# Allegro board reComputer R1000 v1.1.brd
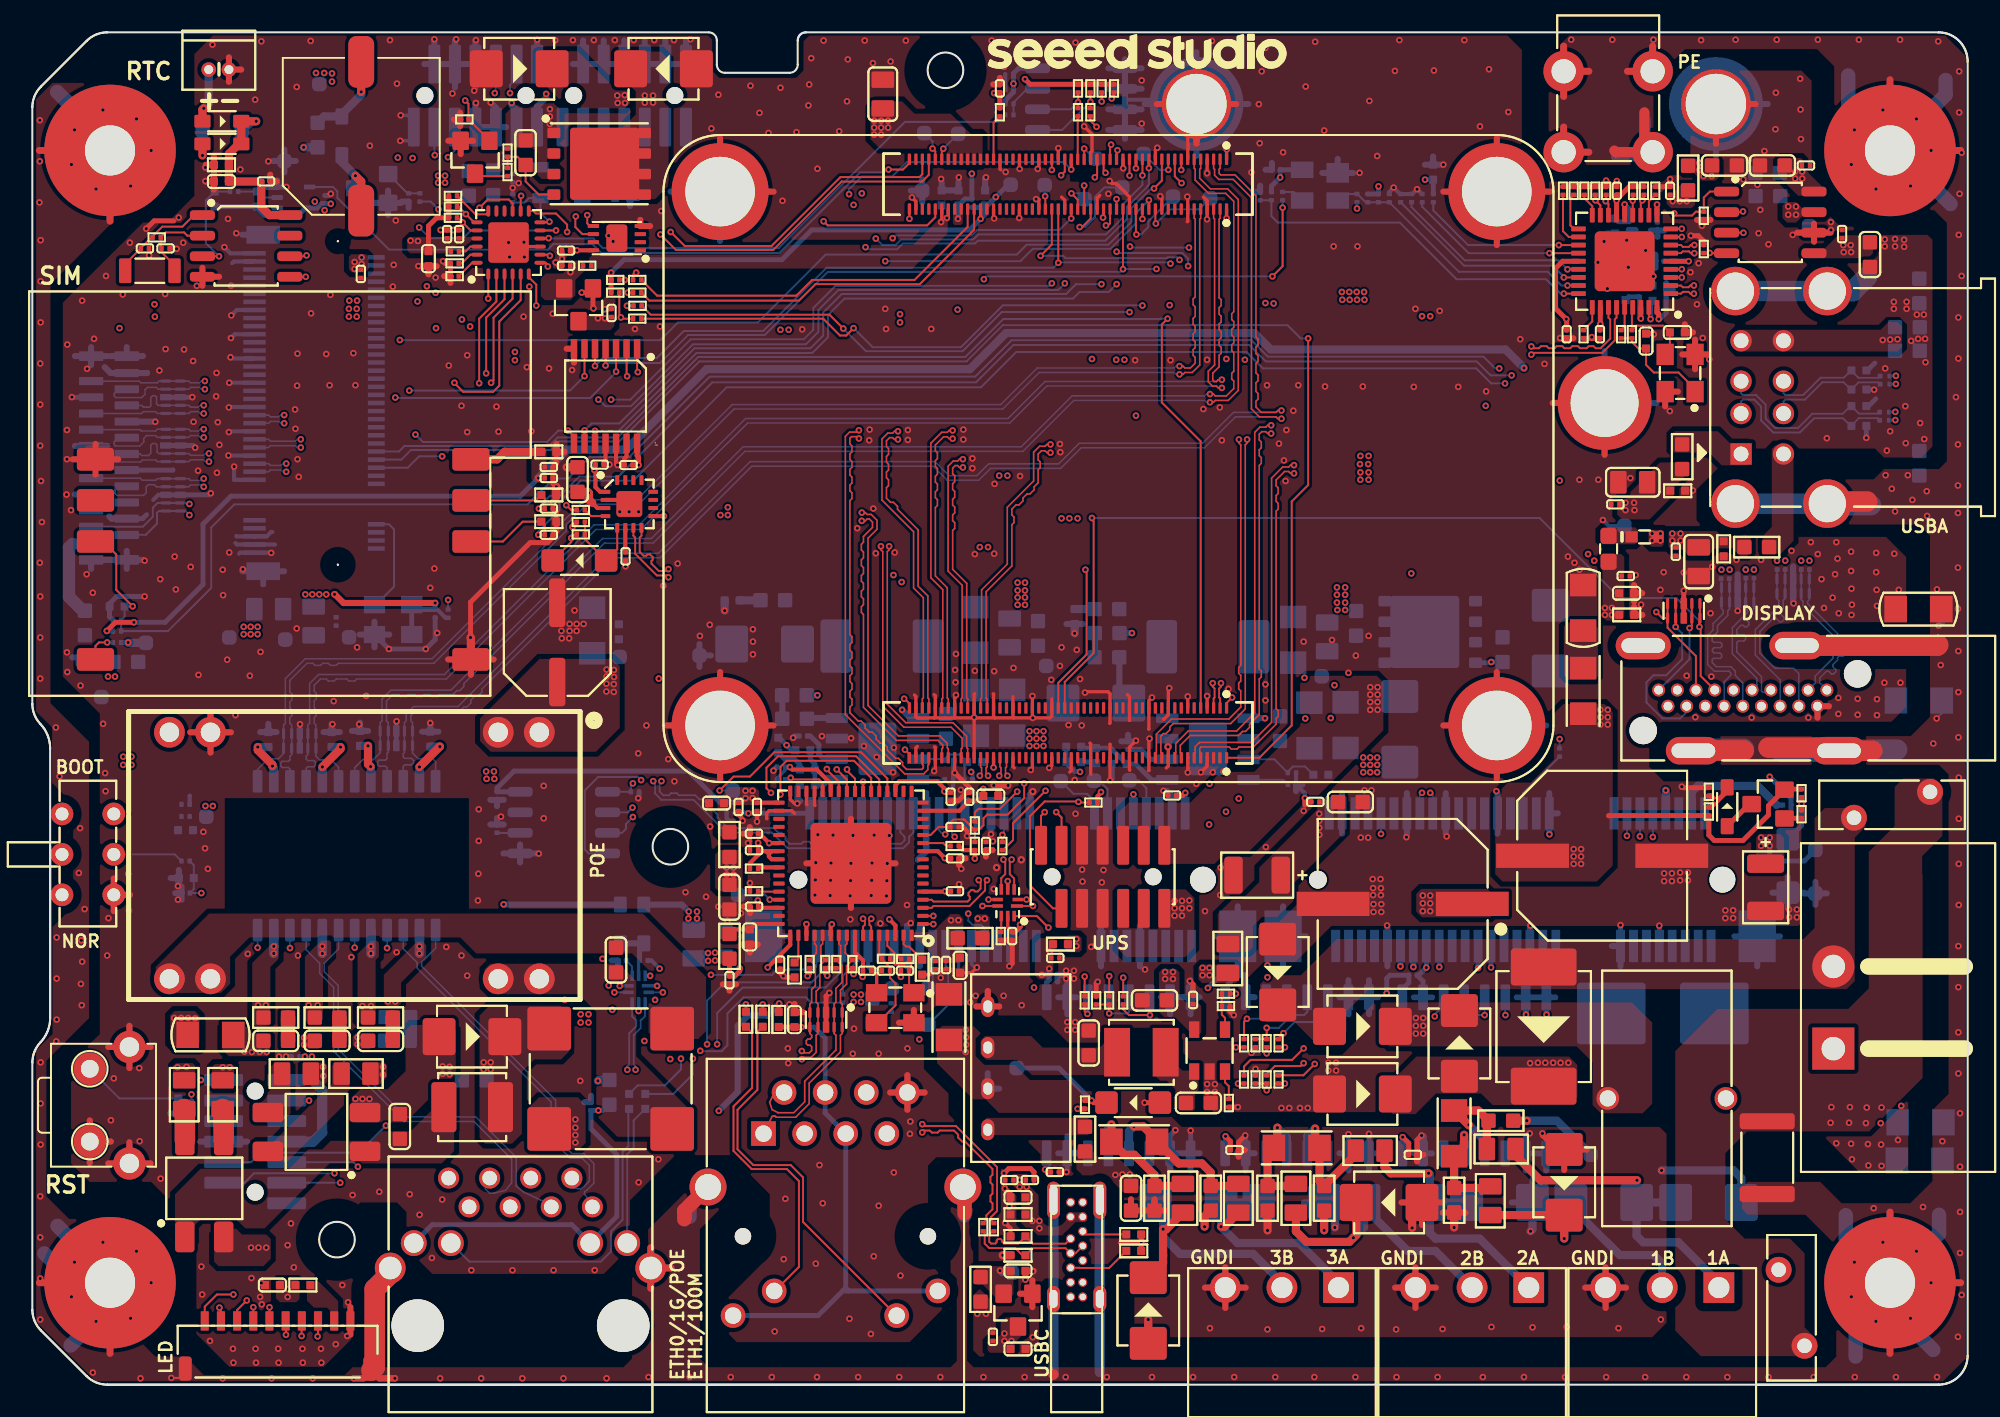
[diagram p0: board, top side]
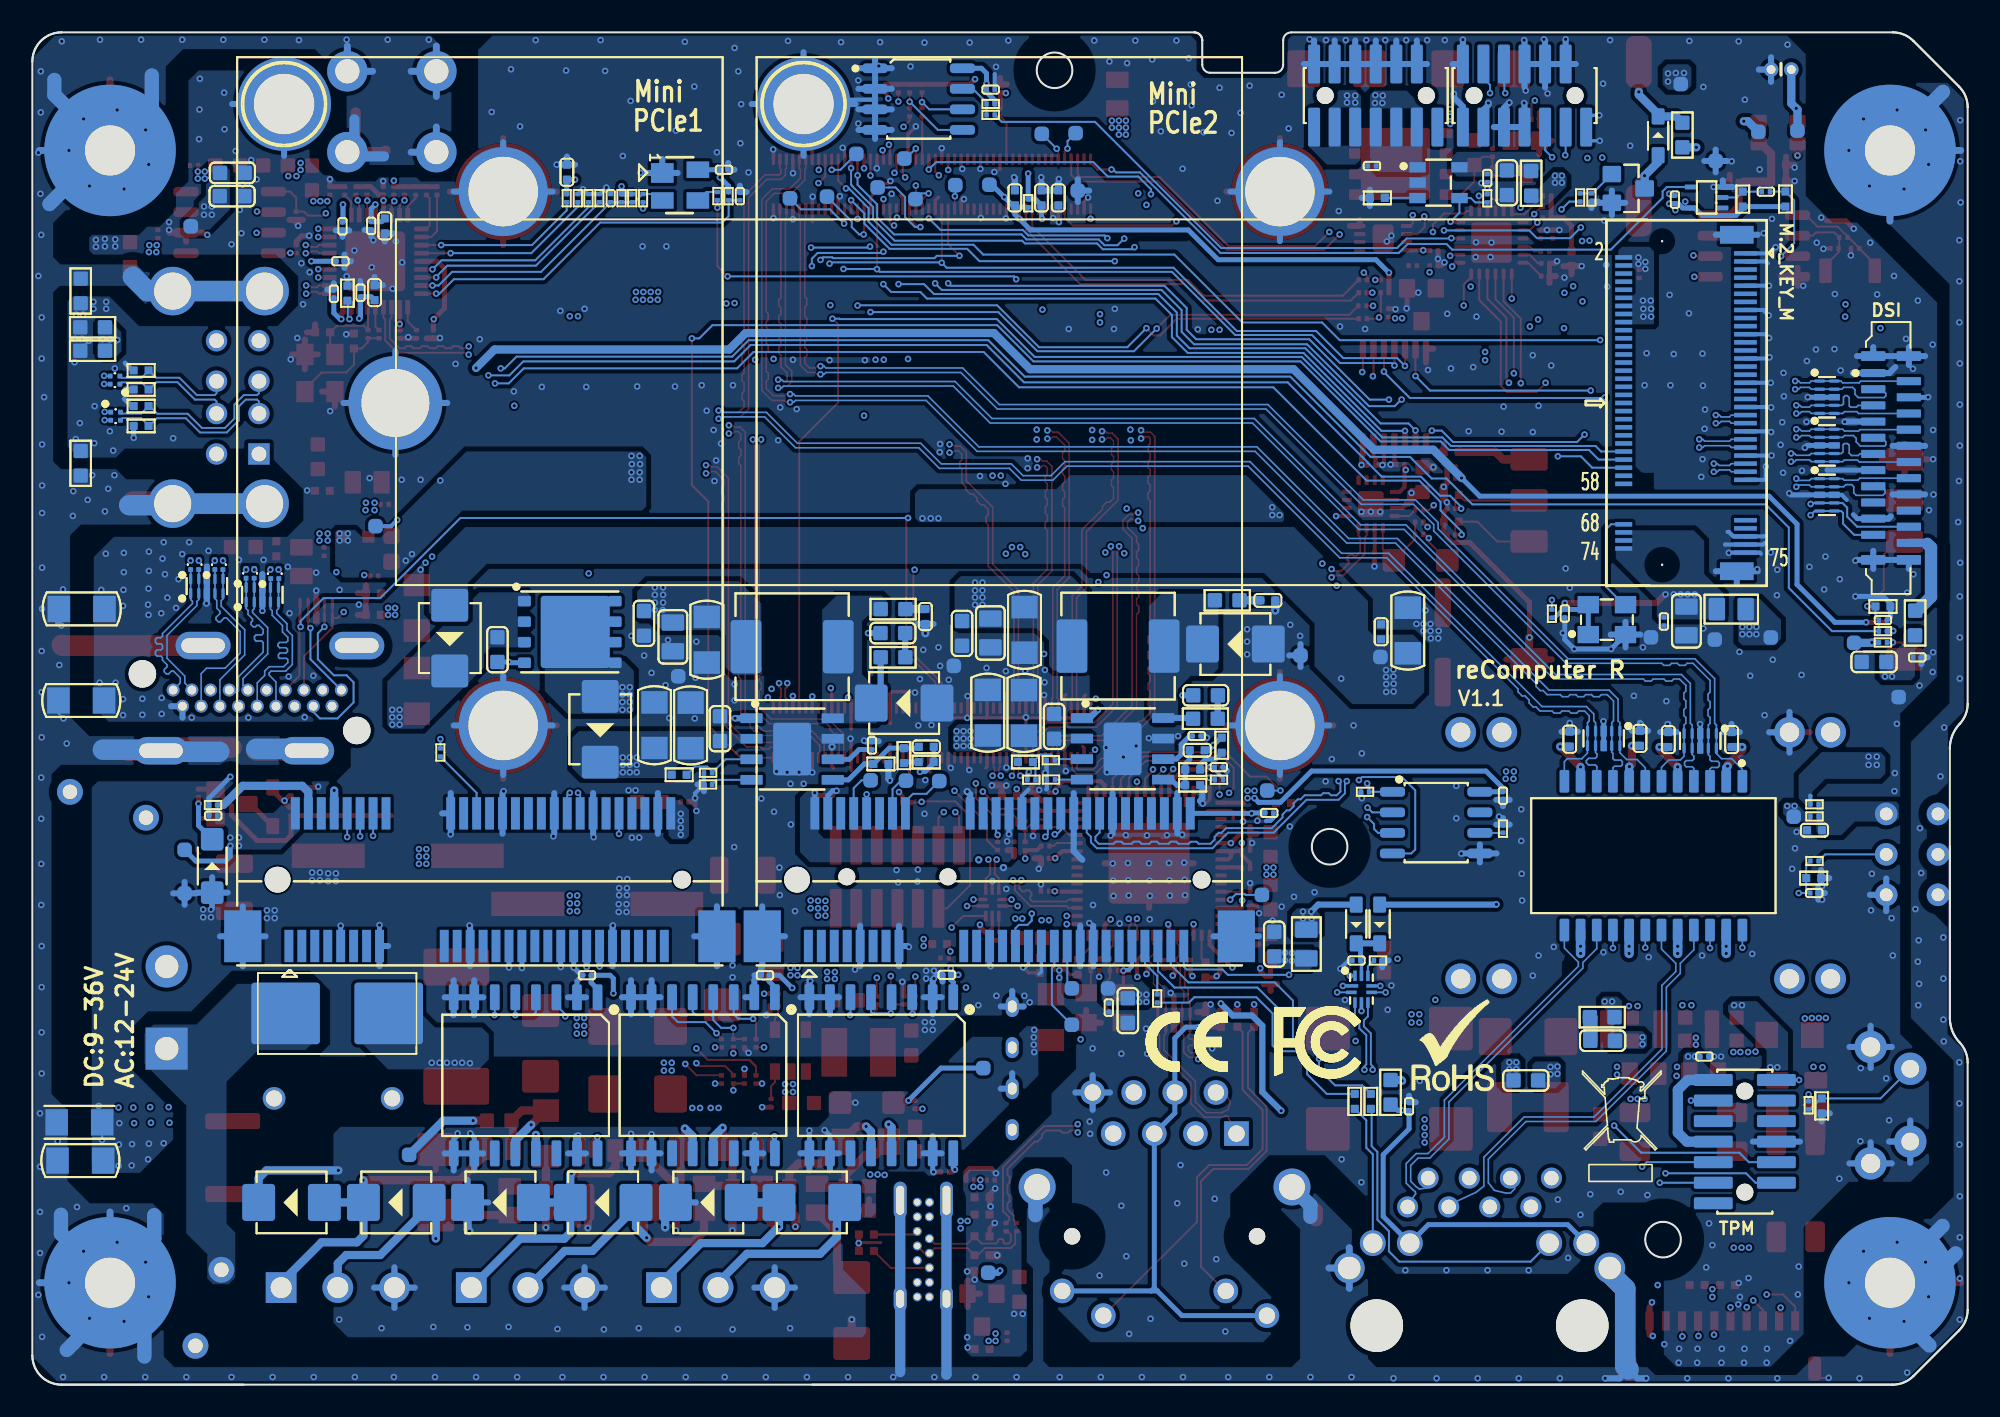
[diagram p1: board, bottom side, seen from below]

Outline 119.6 x 83.6 mm; copper layers: TOP, LYR2_GND, LYR3, LYR4_GND, LYR5_PWR, LYR6, LYR7_GND, BOTTOM. Coordinates in mm from the lower left corner of the outline.
Outline path: circle c18.82,8.97 r1.1 ; circle c18.82,8.97 r1.1 ; circle c39.43,33.26 r1.1 ; circle c39.43,33.26 r1.1 ; circle c56.43,81.25 r1.1 ; circle c56.43,81.25 r1.1 ; 0,78.97 0,42.09 ; 0,78.97 arc(0.14,79.66) 0.53,80.24 ; 0,78.97 arc(0.14,79.66) 0.53,80.24 ; 0,42.09 arc(0.13,41.42) 0.5,40.85 ; 0,42.09 arc(0.13,41.42) 0.5,40.85 ; 0.53,80.24 3.36,83.07 ; 0.53,80.24 3.36,83.07 ; 0,19.91 0,4.63 ; 0,19.91 arc(0.13,20.58) 0.5,21.15 ; 0,19.91 arc(0.13,20.58) 0.5,21.15 ; 0,4.63 arc(0.14,3.94) 0.53,3.36 ; 0,4.63 arc(0.14,3.94) 0.53,3.36 ; 0.5,21.15 arc(0.94,21.85) 1.1,22.67 ; 0.5,21.15 arc(0.94,21.85) 1.1,22.67 ; 0.5,40.85 arc(0.94,40.15) 1.1,39.33 ; 0.5,40.85 arc(0.94,40.15) 1.1,39.33 ; 1.1,39.33 1.1,22.67 ; 3.36,83.07 arc(3.94,83.46) 4.63,83.6 ; 3.36,83.07 arc(3.94,83.46) 4.63,83.6 ; 0.53,3.36 3.36,0.53 ; 0.53,3.36 3.36,0.53 ; 3.36,0.53 arc(3.94,0.14) 4.63,0 ; 3.36,0.53 arc(3.94,0.14) 4.63,0 ; 1.1,22.67 1.1,33.26 ; 4.63,83.6 41.8,83.6 arc(42.15,83.45) 42.3,83.1 42.3,81.6 arc(42.45,81.25) 42.8,81.1 46.8,81.1 arc(47.15,81.25) 47.3,81.6 47.3,83.1 ; 4.63,0 71.42,0 ; 4.63,0 117.8,0 ; 117.8,0 106.52,0 ; 117.8,0 arc(119.07,0.53) 119.6,1.8 ; 117.8,0 arc(119.07,0.53) 119.6,1.8 ; 47.3,83.1 arc(47.45,83.45) 47.8,83.6 ; 47.3,83.1 arc(47.45,83.45) 47.8,83.6 ; 47.8,83.6 117.8,83.6 ; 117.8,83.6 arc(119.07,83.07) 119.6,81.8 ; 117.8,83.6 arc(119.07,83.07) 119.6,81.8 ; 119.6,81.8 119.6,1.8

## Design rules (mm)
constraint set DEFAULT: min track width 0.121
net group CM4_UART2_RXD: nets CM4_UART2_RXD UART2_RXD
net group CM4_UART2_TXD: nets CM4_UART2_TXD UART2_TXD
net group CM4_UART3_RXD: nets CM4_UART3_RXD N23430020
net group CM4_UART3_TXD: nets CM4_UART3_TXD N23430129
net group CM4_UART4_RXD: nets CM4_UART4_RXD N23431044
net group CM4_UART4_TXD: nets CM4_UART4_TXD N23431153
net group DP_HDMI0_CLK_N1: nets HDMI0_CLK_N HDMI0_CLK_P
net group DP_HDMI0_TX0: nets HDMI0_TX0_N HDMI0_TX0_P
net group DP_HDMI0_TX1_N1: nets HDMI0_TX1_N HDMI0_TX1_P
net group DP_HDMI0_TX2_N1: nets HDMI0_TX2_N HDMI0_TX2_P
net group DSI1_C_N: nets DSI1_C_N DSI1_C_P
net group DSI1_D0_N: nets DSI1_D0_N DSI1_D0_P
net group DSI1_D1_P: nets DSI1_D1_N DSI1_D1_P
net group DSI1_D2_N: nets DSI1_D2_N DSI1_D2_P
net group DSI1_D3_N: nets DSI1_D3_N DSI1_D3_P
net group ETHERNET0: nets ETHERNET_PAIR0_N ETHERNET_PAIR0_P
net group ETHERNET1: nets ETHERNET_PAIR1_N ETHERNET_PAIR1_P
net group ETHERNET2: nets ETHERNET_PAIR2_N ETHERNET_PAIR2_P
net group ETHERNET3: nets ETHERNET_PAIR3_N ETHERNET_PAIR3_P
net group ETHERNET_RX_P: nets ETHERNET_RX_N ETHERNET_RX_P
net group ETHERNET_TX_P: nets ETHERNET_TX_N ETHERNET_TX_P
net group HDMI0_CLK_N1: nets HDMI0_CLK_N1 HDMI0_CLK_P1
net group HDMI0_TX0_N1: nets HDMI0_TX0_N1 HDMI0_TX0_P1
net group HDMI0_TX1_N1: nets HDMI0_TX1_N1 HDMI0_TX1_P1
net group HDMI0_TX2_N1: nets HDMI0_TX2_N1 HDMI0_TX2_P1
net group N21891930: nets N21891930 N21894342
net group N23452005: nets N23452005 N23452027
net group PCIE_CLK: nets PCIE_CLK_N PCIE_CLK_P
net group PCIE_RX: nets PCIE_RX_N PCIE_RX_P
net group PCIE_TX: nets PCIE_TX_N PCIE_TX_P
net group RJ_12: nets N22026897 N22026906
net group RJ_36: nets N22026915 N22078660
net group RJ_45: nets N22078676 N22078685
net group RJ_78: nets N22026957 N22026966
net group RS485_2: nets EXT_RS485_2_A EXT_RS485_2_B
net group USB_0: nets USB_0M USB_0P
net group USB_1P: nets USB_1M USB_1P
net group USB_D: nets USB_DM USB_DP
net group USB_HUB1_DM2: nets USB_HUB1_DM2 USB_HUB1_DP2
net group USB_HUB1_DM3: nets USB_HUB1_DM3 USB_HUB1_DP3
net group USB_HUB2_D1: nets USB_HUB2_DM1 USB_HUB2_DP1
net group USB_HUB2_D2: nets USB_HUB2_DM2 USB_HUB2_DP2
net group USB_HUB2_D3: nets USB_HUB2_DM3 USB_HUB2_DP3
net group USB_HUB2_D4: nets USB_HUB2_DM4 USB_HUB2_DP4
net group USB_HUB2_DP1_01: nets N23711005 N23711301
net group USB_HUB2_DP2_01: nets N23452966 N23452985
net group USB_TO_UART: nets USB_TO_UART_DM USB_TO_UART_DP
net group USBC: nets USB_C_DM USB_C_DP
net group USBC_DM: nets USBC_DM USBC_DP
net group VDD33_HUB1: nets N23370571 N23401903
net group 5V_ISO_OUT: nets RS485_1_A RS485_2_A RS485_3_A
net group +3.3V_OUT: nets +3.3V_OUT CM4_GPIO_VREF SD_VDD_OVERRIDE
net group RS485_1: nets RS485_3_B

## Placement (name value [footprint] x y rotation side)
B1  HPD-9603S-3  [BUZZER2P_8D4_9_6X9_6X5_5MM]  20.32 77.18 0 top
C1  100nF  [C0603]  90.86 45.44 270 bottom
C2  220uF  [CAE-10_5X10_5X10_5MM-S]  97.01 32.7 0 top
C3  4.7uF  [C1206]  95.84 48.03 90 top
C5  100nF  [C0603]  66.42 46.46 180 bottom
C6  4.7uF  [C0402]  59.23 36.39 0 top
C7  10uF  [C1206]  78.92 40.76 90 bottom
C8  10uF  [C1206]  81.16 40.77 90 bottom
C9  100nF  [C0603]  77.11 40.55 90 bottom
C10  100nF  [C0603]  81.81 47.07 270 bottom
C11  22uF  [C0805]  80.02 46.23 270 bottom
C12  100uF  [C1206]  77.92 46.05 270 bottom
C13  100uF  [C1206]  58.29 46.66 270 bottom
C14  100nF  [C0201]  44.59 34.06 180 top
C15  10nF  [C0201]  67.71 39.52 90 bottom
C16  150pF  [C0402]  64.41 47.49 270 bottom
C17  150pF  [C0402]  64.35 39.43 0 bottom
C18  100nF  [C0603]  47.09 42.62 180 bottom
C19  100nF  [C0201]  57.9 36.35 90 top
C20  10uF  [C1206]  60.56 41.54 90 bottom
C21  10uF  [C1206]  58.32 41.53 90 bottom
C22  100nF  [C0603]  56.46 40.69 90 bottom
C23  100nF  [C0603]  62.15 46.44 270 bottom
C24  22uF  [C0805]  60.39 46.47 270 bottom
C28  10nF  [C0201]  47.64 40.1 180 bottom
C29  150pF  [C0402]  43.25 48.48 180 bottom
C30  150pF  [C0402]  47.61 39.22 0 bottom
C31  22uF  [C0805]  52.56 79.78 90 top
C32  100nF  [C0201]  59.79 80.13 90 top
C33  10uF  [C0402]  57.23 73.37 270 bottom
C34  10uF  [C0402]  56.2 73.37 270 bottom
C35  1uF  [C0402]  58.88 73.37 270 bottom
C36  1uF  [C0402]  9.47 34.28 0 bottom
C37  100nF  [C0201]  9.48 30.39 180 bottom
C38  100nF  [C0201]  60.56 27.73 270 top
C40  100nF  [C0201]  46.28 38.18 180 bottom
C41  100nF  [C0201]  44.78 35.71 270 top
C42  10uF  [C0603]  43.08 30.14 270 top
C43  100nF  [C0201]  43.64 35.71 270 top
C44  4.7uF  [C0402]  42.28 35.95 180 top
C45  100nF  [C0201]  44.6 29.56 180 top
C46  100nF  [C0201]  44.6 33.04 180 top
C47  100nF  [C0201]  56.75 36.35 270 top
C48  4.7uF  [C0402]  57.33 25.92 270 top
C49  100nF  [C0201]  55.8 25.94 270 top
C50  100nF  [C0201]  51.59 25.59 0 top
C51  100nF  [C0201]  57.02 32.54 0 top
C52  100nF  [C0201]  56.47 25.94 270 top
C53  100nF  [C0201]  46.21 25.97 270 top
C54  100nF  [C0201]  57.02 30.5 0 top
C55  100nF  [C0201]  56.99 34.48 0 top
C56  12pF  [C0201]  53.93 25.59 180 top
C57  12pF  [C0201]  52.75 25.59 180 top
C58  10uF  [C0603]  104.57 75.37 0 top
C59  100nF  [C0201]  101.21 73.81 90 top
C60  100nF  [C0201]  75.88 73.47 90 bottom
C61  100nF  [C0201]  83.86 73.35 90 bottom
C62  100nF  [C0201]  100.43 71.61 270 bottom
C63  100nF  [C0201]  96.88 64.94 270 top
C64  100nF  [C0201]  94.82 64.94 270 top
C65  100nF  [C0201]  100.56 69.45 180 bottom
C66  100nF  [C0201]  100.97 67.44 90 bottom
C67  100nF  [C0201]  97.92 73.81 90 top
C68  100nF  [C0201]  76.86 75.11 180 bottom
C69  1uF  [C0402]  98.45 67.51 270 bottom
C70  10nF  [C0201]  99.32 67.5 270 bottom
C71  1uF  [C0402]  97.82 71.64 90 bottom
C72  10nF  [C0201]  98.66 71.64 90 bottom
C73  1uF  [C0402]  86.57 74.96 90 bottom
C74  27pF  [C0402]  99.73 64.52 90 top
C75  27pF  [C0402]  101.66 65.05 0 top
C76  10uF  [C0805]  98.9 55.79 0 top
C77  10uF  [C0805]  102.98 50.88 270 top
C78  100nF  [C0201]  97.83 54.42 0 top
C79  100nF  [C0201]  101.56 51.5 270 top
C80  10uF  [C0603]  107.26 73.47 180 bottom
C81  10uF  [C0603]  107.24 74.91 180 bottom
C82  10uF  [C0603]  107.53 75.37 180 top
C83  100nF  [C0201]  109.61 75.37 0 top
C84  10uF  [C0603]  113.56 69.86 270 top
C85  100nF  [C0201]  111.84 71.13 90 top
C86  100nF  [C0201]  98.47 49.99 0 top
C87  1uF  [C0402]  98.52 48.92 0 top
C88  22nF  [C0402]  47.1 22.57 90 top
C89  1uF  [C0402]  24.48 69.61 270 top
C90  100nF  [C0201]  26.38 71.13 90 top
C91  100nF  [C0201]  25.63 71.13 90 top
C92  1uF  [C0402]  60.91 11.58 180 top
C93  100nF  [C0201]  61.65 12.65 0 top
C94  100nF  [C0201]  60.38 12.65 180 top
C95  1uF  [C0402]  60.91 2.21 0 top
C96  100nF  [C0201]  59.36 2.96 90 top
C97  1uF  [C0402]  60.91 7.03 0 top
C98  100nF  [C0201]  37.77 26.22 0 bottom
C99  10uF  [C0603]  33.69 55.95 270 top
C100  100nF  [C0201]  35.06 56.87 180 top
C101  100nF  [C0201]  36.66 51.2 90 top
C102  18pF  [C0201]  8.23 70.24 180 top
C103  18pF  [C0201]  6.95 70.24 0 top
C104  1uF  [C0402]  11.68 74.38 180 top
C105  100nF  [C0201]  14.44 74.39 0 top
C106  100nF  [C0201]  16.27 20.28 180 bottom
C107  100nF  [C0201]  60.38 80.06 180 bottom
C108  100nF  [C0201]  18.09 73.26 90 bottom
C109  100nF  [C0201]  12.47 73.75 0 bottom
C110  100nF  [C0201]  32.98 70.11 0 top
C111  100nF  [C0201]  108.43 35.17 0 bottom
C112  100nF  [C0201]  70.44 36.42 0 top
C113  100nF  [C0201]  53.08 23.31 90 bottom
C114  100nF  [C0201]  43.16 35.34 0 bottom
C115  100nF  [C0201]  35.79 66.26 270 top
C116  100nF  [C0201]  32.99 69.17 0 top
C117  10uF  [C0603]  42.85 27.23 90 bottom
C118  10uF  [C0603]  51.9 23.13 270 bottom
C119  100nF  [C0201]  58.93 33.3 270 top
C120  100nF  [C0201]  31.92 56.73 0 top
C121  33pF  [C0201]  31.92 56.05 0 top
C122  33pF  [C0201]  5.23 47.27 180 bottom
C123  33pF  [C0201]  31.92 52.54 0 top
C124  10uF  [C0603]  81.45 36.02 0 top
C125  100nF  [C0201]  79.29 36.03 180 top
C126  47uF  [AVX_B]  75.69 31.5 180 top
C127  47uF  [AVX_B]  107.11 30.75 270 top
C128  33pF  [C0201]  31.92 54.16 0 top
C130  10uF  [C0603]  69.35 23.76 180 top
C131  100nF  [C0201]  71.73 23.78 90 top
C132  10uF  [C0603]  72.06 17.42 0 top
C133  10uF  [C0603]  65.28 21.12 90 top
C134  10uF  [C0603]  67.9 11.52 270 top
C136  100nF  [C0201]  63.22 26.38 0 top
C137  100nF  [C0201]  85.32 25.31 0 bottom
C138  100nF  [C0201]  85.32 14.21 0 top
C139  100nF  [C0201]  36.84 56.85 180 top
C140  100nF  [C0201]  74.32 25.31 0 bottom
C141  100nF  [C0201]  74.29 14.51 0 top
C142  100nF  [C0201]  63.1 25.34 0 bottom
C143  100nF  [C0201]  63.19 13.15 0 top
C144  100uF  [ELECTRO_SMD_6_6X6_6MM]  32.44 45.88 0 top
C145  10uF  [C1206]  34.6 46.62 90 bottom
C146  100nF  [C0402]  36.25 46.54 90 bottom
C147  10nF  [C0603]  36.07 26.25 90 top
C148  10nF  [C0603]  27.31 18.81 180 bottom
C149  10nF  [C0603]  22.71 15.96 90 top
C150  100nF  [C0402]  14.58 39.88 90 bottom
C151  100nF  [C0402]  18.5 39.88 90 bottom
C152  100nF  [C0402]  20.25 39.96 90 bottom
C153  100nF  [C0402]  24.59 39.91 90 bottom
C154  22nF  [C0603]  15.04 21.26 180 top
C155  22nF  [C0603]  18.21 21.26 180 top
C156  22nF  [C0603]  21.52 21.26 180 top
C157  22nF  [C0603]  22.56 21.26 180 bottom
C158  1nF  [C1206]  11.01 21.62 180 top
C159  1nF  [C1206]  116.63 13.85 0 bottom
C160  100nF  [C0201]  34.52 17.21 90 bottom
C161  100nF  [C0201]  36.81 75.34 0 bottom
C162  100nF  [C0603]  30.48 76.16 270 top
C163  4.7uF  [C0402]  14.84 6.16 180 top
C164  10uF  [C0603]  28.48 74.3 270 bottom
C165  100nF  [C0201]  29.69 74.59 270 bottom
C166  22uF  [C0805]  17.38 47.21 270 bottom
C167  100nF  [C0201]  18.77 47.18 270 bottom
C168  100nF  [C0201]  24.89 47.67 270 bottom
C169  100nF  [C0201]  20.3 68.67 270 top
C499  220uF  [CAE-10_5X10_5X10_5MM-S]  84.69 29.72 180 top
C500  100nF  [C0201]  28.72 36.41 270 bottom
C501  100nF  [C0201]  43.08 25 270 top
C502  1uF  [C0402]  44.33 27.68 270 top
C503  10uF  [C0603]  5.78 44.68 0 bottom
C504  100nF  [C0201]  3.11 44.96 180 bottom
C505  1nF  [C1206]  116.58 42.29 0 bottom
C506  10nF  [C1206]  116.55 47.96 0 bottom
C507  10nF  [C1206]  116.56 47.94 0 top
D1  SM360B  [DO_214AA_SMB]  93.8 46.15 270 bottom
D2  SM360B  [DO_214AA_SMB]  84.51 40.51 270 bottom
D3  SM360B  [DO_214AA_SMB]  88.19 21.09 90 top
D4  SM360B  [DO_214AA_SMB]  82.2 22.15 0 top
D5  SMCJ40A  [DO_214AB_SMC]  93.4 22.14 270 top
D6  SM360B  [DO_214AA_SMB]  82.2 17.97 0 top
D7  SM360B  [DO_214AA_SMB]  76.96 25.51 270 top
D8  MMSZ5259A  [SOD_123]  108.49 32.07 90 bottom
D9  B5819WS SL  [SOD_323]  104.74 35.72 90 top
D10  SM360B  [DO_214AA_SMB]  65.73 42.14 0 bottom
D11  SM360B  [DO_214AA_SMB]  45.25 45.78 0 bottom
D12  ESDPSA0402V05  [D0402]  9.02 17.23 90 bottom
D13  B5819WS SL  [SOD_323]  19.13 77.2 90 bottom
D14  ESDPSA0402V05  [D0402]  112.88 60.5 180 bottom
D15  ESDPSA0402V05  [D0402]  112.88 59.27 180 bottom
D16  ESDPSA0402V05  [D0402]  101.68 55.26 180 top
D17  ESDPSA0402V05  [D0402]  104.52 51.67 90 top
D18  ESDPSA0402V05  [D0402]  112.88 61.52 180 bottom
D19  ESDPSA0402V05  [D0402]  112.88 62.7 180 bottom
D20  ESDPSA0402V05  [D0402]  98.53 47.59 180 top
D21  ESDPSA0402V05  [D0402]  60.91 10.52 0 top
D22  ESDPSA0402V05  [D0402]  60.91 8 0 top
D23  ESDPSA0402V05  [D0402]  60.91 9.17 0 top
D24  B5819WS SL  [SOD_323]  36.34 28.48 270 bottom
D25  B5819WS SL  [SOD_323]  37.79 28.48 270 bottom
D26  B0540W  [SOD_123]  33.81 50.95 180 top
D27  B5819WS SL  [SOD_323]  11.71 76.71 0 top
D28  ESDPSA0402V05  [D0402]  11.69 75.41 0 top
D29  B5819WS SL  [SOD_323]  11.71 78.1 0 top
D30  TPD1E1B04DPYR  [D0402]  5.23 48.11 0 bottom
D31  TPD1E1B04DPYR  [D0402]  31.92 53.35 180 top
D32  TPD1E1B04DPYR  [D0402]  31.92 55 180 top
D33  TPD1E1B04DPYR  [D0402]  31.92 57.67 180 top
D34  MMSZ5232BT1G  [SOD_123]  68.03 17.43 180 top
D36  SMBJ13CATR7  [DO_214AA_SMB]  103.58 11.26 0 bottom
D37  SMBJ13CATR7  [DO_214AA_SMB]  97.11 11.26 0 bottom
D39  SMBJ13CATR7  [DO_214AA_SMB]  94.67 12.51 270 top
D41  SMBJ13CATR7  [DO_214AA_SMB]  90.67 11.26 0 bottom
D42  SMBJ13CATR7  [DO_214AA_SMB]  84.33 11.26 0 bottom
D44  SMBJ13CATR7  [DO_214AA_SMB]  83.85 11.26 180 top
D46  SMBJ13CATR7  [DO_214AA_SMB]  77.83 11.26 0 bottom
D47  SMBJ13CATR7  [DO_214AA_SMB]  71.43 11.26 0 bottom
D48  SMBJ13CATR7  [DO_214AA_SMB]  68.96 4.58 90 top
D50  SMBJ58CA  [DO_214AA_SMB]  27.17 21.51 0 top
D51  MB6S  [SMD4P_4D7X3D8MM]  10.62 12.13 180 top
D52  MB6S  [SMD4P_4D7X3D8MM]  17.56 15.62 270 top
D61  SMBJ36CA  [DO_214AA_SMB]  39.01 81.35 180 top
D62  SMBJ5.0CA-TR  [DO_214AA_SMB]  30.09 81.35 0 top
D63  LRB520S-30T1G  [SOD_523]  99.64 52.41 180 top
F1  5A  [FUSE2P_HOLDER_9_73X5_03X3_81MM]  100.76 22.95 180 bottom
F2  100mA  [F0603]  97.41 51.67 90 top
FB1  120R  [L0603]  43.08 33.39 90 top
FB2  120R  [L0603]  57.95 27.6 180 top
FB3  120R  [L0603]  43.08 27.1 270 top
FB4  120R  [L0603]  102.33 74.6 270 top
FB5  120R  [L0603]  101.96 57.37 90 top
FB6  120R  [L0603]  106.56 51.78 180 top
FB9  120R  [L0603]  35.66 18.07 270 bottom
FB10  120R  [L0603]  26.98 74.27 90 bottom
FB26  120R  [L0603]  3.24 47.09 270 bottom
FB27  120R  [L0402]  16.72 6.16 180 top
G1  4532-201-LF  [GDT2P_4D0_4_5X3_2X2_7MM]  107.22 14.03 90 top
J1  STP2EDGRM-X-5.08-2P  [TERMINAL_2P_5D08]  111.3 23.31 90 top
J2  Header 2x7Pin 1.27MM  [HEADER2X7P_1D27_SMD_NP_EPT14]  66.14 31.4 180 top
J3  PCB-69-M3  [SOLDERING_TERMINAL_4P_9X6_3X5MM]  97.38 78.69 270 top
J4  DF40C-100DS-0.4V(51)  [DF40_100P_0D4_22_6X3_38X1_5MM]  64 74.21 90 top
J5  DF40C-100DS-0.4V(51)  [DF40_100P_0D4_22_6X3_38X1_5MM_101_200]  64 40.29 90 top
J6  Toggle Switch_2CH  [SW6P_2D5_9X3_5X3_5MM]  3.43 32.78 270 top
J8  USB-AF-90  [ST-USB-201C]  110.93 61.03 270 top
J9  TYPE_A  [HDMI19P_1D155_23_1X7_7X16_4MM]  112.8 42.44 90 top
J10  LPJ0011BBNL  [RJ45-7499010211A]  45.19 15.52 0 top
J11  UBF31-112-14C1-024  [USB2_0_TYPE_C_14X3D16X8D94MM]  64.54 8.35 270 top
J12  Header 1x2 1.25mm  [HEADER2P_1D25_DIP]  11.52 81.3 0 top
J13  Header 2x7Pin 1.27MM  [HEADER2X7P_1D27_SMD_NP_EPT14]  13.77 15.02 270 bottom
J14  ST-PC-009  [PCIE52_0D8_56X30_2X4MM]  59.84 31.22 90 bottom
J15  ST-PC-009  [PCIE52_0D8_56X30_2X4MM]  91.95 31.22 90 bottom
J16  ST-SIM-10CY  [SIM6_2P_2D54_25X31X3_55MM]  3.9 57.2 270 top
J18  DGKYD56A1188AB1A2DY1054  [RJ45_12_2P_2D54_16_3X15_8X12_85MM]  30.17 3.65 0 top
J19  Header 2x7Pin 1.27MM  [HEADER2X7P_1D27_SMD_NP_EPT14]  36.58 79.69 180 bottom
J21  HQ15EDGRC-3.5-03P-040  [TERMINAL_3P_3D5_11_6X9_2X7_3MM]  100.72 6 180 top
J22  HQ15EDGRC-3.5-03P-040  [TERMINAL_3P_3D5_11_6X9_2X7_3MM]  88.97 6 180 top
J23  HQ15EDGRC-3.5-03P-040  [TERMINAL_3P_3D5_11_6X9_2X7_3MM]  77.22 6 180 top
J24  MTFP65-822SWN-19A72  [FPC22_0D5_16_7X3_5X3_95MM_90D]  4.73 57.29 90 bottom
J25  1.0-10A-LT  [JST10_2P_1D0_12_35X3_2X4_5MM]  15.15 3.94 0 top
J61  Header 2x7Pin 1.27MM  [HEADER2X7P_1D27_SMD_NP_EPT14]  27.38 79.69 180 bottom
J62  2E0BC26-F20BM-7H  [CON_MINIPEX_075_SMT_RA_M2_KEYM]  17.55 60.69 270 bottom
L2  10uH  [L6_6X7X1_6MM]  72.65 45.62 0 bottom
L3  10uH  [L6_6X7X1_6MM]  52.5 45.66 0 bottom
L4  90R  [L4P_0_85X0_65MM]  114.46 59.87 270 bottom
L5  90R  [L4P_0_85X0_65MM]  114.49 62.1 90 bottom
L11  6.8uH  [L4X4MM]  68.54 20.55 180 top
L15  3.3uH  [L4242]  27.18 17.16 180 top
L16  3200R  [L4P_10X8_7X6_5MM]  35.74 18.91 270 top
L18  XR050125T101MVL7  [L2P_7D3_15_8X8X10MM]  101.01 17.7 0 top
L19  90R  [L4P_0_85X0_65MM]  109.57 50.69 180 bottom
L20  90R  [L4P_0_85X0_65MM]  108.07 50.69 180 bottom
L21  90R  [L4P_0_85X0_65MM]  106.14 50.16 180 bottom
L22  90R  [L4P_0_85X0_65MM]  104.62 50.13 180 bottom
MH1  2.5MM  [PTH_4_3MM_6D0]  42.5 73.75 0 top
MH2  2.5MM  [PTH_4_3MM_6D0]  42.5 40.75 0 top
MH3  2.5MM  [PTH_4_3MM_6D0]  90.5 40.75 0 top
MH4  2.5MM  [PTH_4_3MM_6D0]  90.5 73.75 0 top
MH6  SMTSO2066CTJ  [PTH_3_73MM_5D8_PASTE]  71.94 79.17 180 bottom
MH7  SMTSO3003CTJ  [PTH_4_2MM_5D8]  97.16 60.69 180 bottom
MH10  SMTSO2066CTJ  [PTH_3_73MM_5D8_PASTE]  104.04 79.17 180 bottom
MH11  Hole 3.1MM  [PTH_3_1MM_8]  4.8 76.3 0 top
MH12  Hole 3.1MM  [PTH_3_1MM_8]  4.8 6.3 0 top
MH13  Hole 3.1MM  [PTH_3_1MM_8]  114.8 6.3 0 top
MH14  Hole 3.1MM  [PTH_3_1MM_8]  114.8 76.3 0 top
NOREF  -  []  0 78.97 0 top
NOREF#2  -  []  4.63 0 90 top
NOREF#3  -  []  -307.46 -238.04 0 top
OSC1  32.768KHz  [X4-SMD-3_2X2_5X1_0MM]  22.29 47.29 180 bottom
Q1  CJAC70P06  [SON8P_1D27_5X6X1MM]  86.39 46.53 180 bottom
Q2  MMBT3906LT  [SOT23]  107.27 35.89 90 top
Q3  2N7002,215  [SOT23]  20.97 73.95 270 bottom
Q4  CJAC70P06  [SON8P_1D27_5X6X1MM]  35.03 75.48 0 top
Q5  2N7002,215  [SOT23]  27.36 75.88 180 top
R2  2.2K  [R0201]  109.34 36.56 270 top
R3  100K  [R0201]  103.61 35.43 90 top
R4  10R  [R1206]  95.84 42.89 90 top
R5  10K  [R0201]  109.34 35.27 270 top
R7  200K  [R0201]  103.61 36.65 90 top
R8  51K  [R0402]  79.63 37.7 180 bottom
R9  5.1R  [R0603]  66.41 44.97 0 bottom
R10  100K  [R0201]  77.84 37.83 180 bottom
R11  5.1R  [R0603]  66.41 47.94 180 bottom
R12  49.9K  [R0201]  77.85 37.1 0 bottom
R13  68K  [R0402]  65.74 38.89 90 bottom
R14  12K  [R0402]  67.16 38.37 180 bottom
R15  5.1R  [R0603]  47.11 41.17 0 bottom
R16  51K  [R0402]  58.23 38.49 180 bottom
R17  100K  [R0201]  56.66 38.6 180 bottom
R18  5.1R  [R0603]  45.76 48.49 180 bottom
R19  49.9K  [R0201]  56.65 37.41 0 bottom
R20  68K  [R0402]  47.89 38.02 0 bottom
R21  20K  [R0402]  47.89 37.06 180 bottom
R22  22R  [R0201]  65.38 78.66 270 top
R23  22R  [R0201]  64.62 78.66 90 top
R24  22R  [R0201]  37.38 65.9 0 top
R25  22R  [R0201]  37.4 66.7 180 top
R26  0R  [R0201]  59.79 78.66 90 top
R27  22R  [R0201]  37.38 67.51 0 top
R28  22R  [R0201]  37.38 68.3 0 top
R29  0R  [R0201]  58.06 73.04 90 bottom
R30  4.7K  [R0201]  36.02 67.51 0 top
R31  4.7K  [R0201]  36.02 68.3 0 top
R32  0R  [R0201]  9.47 35.13 0 bottom
R33  0R  [R0201]  9.47 35.88 0 bottom
R34  10K  [R0201]  9.47 32.37 0 bottom
R35  18K  [R0402]  9.51 31.32 180 bottom
R36  0R  [R0201]  9.83 17.27 90 bottom
R37  0R  [R0201]  59.84 27.73 270 top
R38  33R  [R0603]  17.63 77.25 90 bottom
R39  1K  [R0201]  23.95 73.39 90 bottom
R40  100K  [R0201]  23.25 73.39 270 bottom
R41  10K  [R0201]  57 33.3 180 top
R42  12K  [R0402]  54.99 25.81 90 top
R43  10K  [R0201]  44.6 31.9 0 top
R44  10K  [R0201]  58.24 33.3 90 top
R45  12.4K  [R0402]  47.11 25.63 90 top
R46  0R  [R0201]  58.24 34.57 270 top
R47  0R  [R0201]  53.94 26.32 180 top
R48  0R  [R0201]  44.6 30.51 180 top
R49  1M  [R0201]  52.76 26.33 180 top
R50  10K  [R0201]  46.27 37.4 180 bottom
R51  10K  [R0201]  76.57 73.47 270 bottom
R52  10K  [R0201]  83.19 73.35 270 bottom
R53  10K  [R0201]  95.86 64.94 90 top
R54  10K  [R0201]  85.89 73.35 270 bottom
R55  10K  [R0201]  85.23 73.35 270 bottom
R56  10K  [R0201]  84.56 73.35 270 bottom
R57  0R  [R0201]  100.3 73.81 90 top
R58  12K  [R0402]  100.13 67.47 90 bottom
R59  10K  [R0201]  82.53 73.35 270 bottom
R60  10K  [R0201]  98.92 73.81 90 top
R61  10K  [R0201]  96.59 73.81 90 top
R62  10K  [R0201]  95.25 73.81 90 top
R63  10K  [R0201]  86.58 73.35 90 bottom
R64  0R  [R0201]  77.27 73.48 90 bottom
R65  10K  [R0201]  99.6 73.81 90 top
R66  10K  [R0201]  97.26 73.81 90 top
R67  10K  [R0201]  95.91 73.81 90 top
R68  10K  [R0201]  94.59 73.81 90 top
R69  0R  [R0201]  98.18 64.94 90 top
R70  1M  [R0201]  98.85 64.94 90 top
R71  0R  [R0201]  81.86 73.35 90 bottom
R72  0R  [R0603]  115.88 65.37 0 bottom
R73  0R  [R0603]  115.88 63.92 0 bottom
R74  10K  [R0201]  103.29 70.21 270 top
R75  10K  [R0201]  103.29 72.26 90 top
R78  49.9R  [R0201]  50.68 26 90 top
R79  49.9R  [R0201]  49.68 26 90 top
R80  49.9R  [R0201]  49 26 90 top
R81  49.9R  [R0201]  48.04 26 90 top
R82  10R  [R0402]  46.13 22.58 270 top
R83  470R  [R0402]  44.1 22.59 270 top
R84  470R  [R0402]  45.14 22.59 270 top
R85  100K  [R0201]  25.99 73.49 0 top
R88  2.2K  [R0201]  25.99 72.83 0 top
R89  2.2K  [R0201]  25.99 72.14 0 top
R90  4.7K  [R0201]  26.11 70.06 0 top
R92  0R  [R0201]  26.1 69.32 180 top
R93  0R  [R0201]  26.1 68.53 180 top
R94  5.1K  [R0402]  68.06 8.27 0 top
R95  5.1K  [R0402]  68.06 9.29 0 top
R96  1K  [R0603]  58.6 5.89 270 top
R97  0R  [R0201]  36.44 26.22 180 bottom
R98  4.7K  [R0201]  33.89 53.33 0 top
R99  0R  [R0201]  33.89 52.56 180 top
R100  33R  [R0201]  33.89 54.07 180 top
R101  1M  [R0201]  7.68 70.93 180 top
R102  10K  [R0201]  60.38 79.17 0 bottom
R103  0R  [R0201]  60.38 78.5 180 bottom
R104  510K  [R0402]  11.26 73.29 90 bottom
R105  510K  [R0402]  13.9 73.29 90 bottom
R106  4.7K  [R0201]  64.62 80.13 270 top
R107  4.7K  [R0201]  65.38 80.13 270 top
R108  0R  [R0201]  108.43 35.83 0 bottom
R109  0R  [R0201]  94.39 39.08 90 bottom
R110  0R  [R0201]  59.95 33.3 270 top
R111  0R  [R0201]  50.08 23.87 90 bottom
R112  0R  [R0201]  34.29 69.17 0 top
R113  0R  [R0805]  40.87 27.24 270 bottom
R114  10K  [R0201]  5.23 45.88 180 bottom
R115  15K  [R0201]  5.23 46.58 0 bottom
R116  0R  [R0805]  73.88 26.34 90 top
R117  0R  [R0603]  65.05 15.18 270 top
R118  0R  [R0201]  65.05 17.31 90 top
R119  100K  [R0201]  73.76 23.41 0 top
R120  15K  [R0201]  73.94 17.41 270 top
R122  0R  [R0201]  73.76 24.17 180 top
R123  1M  [R1206]  56.64 22.72 270 top
R124  10K  [R0603]  90.75 16.32 180 top
R125  RC0805FR-0710RL  [R0805]  90.78 14.57 0 top
R126  33R  [R0201]  77.01 18.87 270 top
R127  0R  [R0201]  76.28 18.87 270 top
R128  33R  [R0201]  74.88 18.87 270 top
R129  120R  [R1206]  87.86 15.54 270 top
R130  RC0805FR-0710RL  [R0805]  90.1 11.37 270 top
R131  10K  [R0201]  75.59 18.87 90 top
R132  10K  [R0603]  87.86 11.4 270 top
R133  10K  [R0603]  79.83 11.52 90 top
R134  33R  [R0201]  74.88 21.11 90 top
R135  RC0805FR-0710RL  [R0805]  82.67 14.47 0 top
R136  0R  [R0201]  76.28 21.11 90 top
R137  33R  [R0201]  77.01 21.11 90 top
R138  10K  [R0201]  75.59 21.11 270 top
R139  120R  [R1206]  78.13 14.64 180 top
R140  RC0805FR-0710RL  [R0805]  78.09 11.52 270 top
R141  10K  [R0603]  76.33 11.52 270 top
R142  10K  [R0603]  72.82 11.52 90 top
R143  RC0805FR-0710RL  [R0805]  74.53 11.52 270 top
R144  33R  [R0201]  65.03 23.76 270 top
R145  0R  [R0201]  66.55 23.76 270 top
R146  33R  [R0201]  67.41 23.76 270 top
R147  10K  [R0201]  65.74 23.76 90 top
R148  120R  [R1206]  68.09 15.02 180 top
R149  10K  [R0603]  69.35 11.52 270 top
R150  RC0805FR-0710RL  [R0805]  71.1 11.52 270 top
R151  0R  [R0805]  9.39 17.93 90 top
R152  0R  [R0805]  11.76 17.93 90 top
R153  0R  [R0805]  20 19.23 0 top
R154  0R  [R0805]  16.32 19.23 0 top
R155  470R  [R0402]  36.88 17.51 270 bottom
R156  75R  [R0603]  15.04 22.69 0 top
R157  75R  [R0603]  18.21 22.69 0 top
R158  75R  [R0603]  21.52 22.69 0 top
R159  75R  [R0603]  22.58 22.72 0 bottom
R160  470R  [R0402]  37.87 17.51 270 bottom
R161  0R  [R1206]  116.69 16.22 0 bottom
R162  100K  [R0201]  29.36 76.16 270 top
R163  1K  [R0201]  29.36 74.97 90 top
R164  100K  [R0201]  26.7 78.22 180 top
R173  13.3K  [R0402]  36.48 73.37 0 bottom
R174  100K  [R0201]  29.69 73.34 90 bottom
R175  10K  [R0201]  25.69 47.66 90 bottom
R176  0R  [R0805]  14.61 47.94 0 bottom
R177  4.7K  [R0201]  66.84 80.13 270 top
R178  4.7K  [R0201]  66.08 80.13 270 top
R181  0R  [R0201]  57.86 37.4 180 bottom
R182  820KD07  [CAP_5D0_9X3X12MM]  108.72 4.75 270 top
R183  820KD07  [CAP_5D0_9X3X12MM]  114.93 35.85 180 top
R530  22R  [R0201]  59.42 9.74 90 top
R531  22R  [R0201]  58.76 9.74 90 top
R532  0R  [R0402]  63.54 27.23 180 top
R573  10K  [R0201]  37.24 36.65 0 bottom
R632  0R  [R0603]  116.61 56.96 90 bottom
R633  0R  [R0603]  116.61 67.61 270 bottom
R651  0R  [R0201]  28.72 34.37 270 bottom
R652  49.9R  [R0402]  64.36 38.49 0 bottom
R653  49.9R  [R0402]  46.1 39.53 270 bottom
R654  100K  [R0201]  65.57 35.99 180 top
SW1  TC-1105AH-5.0H-250  [BUTTON4P_7_2X7_5X7MM]  6 17.28 90 top
T1  LP82441ANL  [TRF24P_1D0_15_1X7_1X4MM]  19.42 32.7 0 bottom
TP1  Test Point  [TP35S_SMD]  17.73 80.4 90 bottom
TP2  Test Point  [TP35S_SMD]  19.57 46.2 90 bottom
TP3  Test Point  [TP35S_SMD]  4.26 42.51 90 bottom
TP4  Test Point  [TP35S_SMD]  79.68 43.79 180 bottom
TP5  Test Point  [TP35S_SMD]  62.66 44.43 90 bottom
TP6  Test Point  [TP35S_SMD]  41.23 45.08 0 bottom
TP7  Test Point  [TP35S_SMD]  110.19 30.37 0 bottom
TP8  Test Point  [TP35S_SMD]  15.63 46.06 0 bottom
TP9  Test Point  [TP35S_SMD]  98.39 53.07 0 bottom
TP10  Test Point  [TP35S_SMD]  109.81 71.61 270 bottom
TP11  Test Point  [TP35S_SMD]  12.17 46.19 270 bottom
TP12  Test Point  [TP35S_SMD]  68.68 76.08 0 bottom
TP13  Test Point  [TP35S_SMD]  15.57 75.65 270 bottom
TP14  Test Point  [TP35S_SMD]  57.22 77.33 270 bottom
TP15  Test Point  [TP35S_SMD]  55.13 77.37 270 bottom
TP16  Test Point  [TP35S_SMD]  60.45 74.18 180 bottom
TP17  Test Point  [TP35S_SMD]  54.99 73.81 180 bottom
TP18  Test Point  [TP35S_SMD]  43.28 36.73 180 bottom
TP19  Test Point  [TP35S_SMD]  43.61 30.28 180 bottom
TP20  Test Point  [TP35S_SMD]  10.75 35.11 180 bottom
TP21  Test Point  [TP35S_SMD]  60.53 6.92 270 bottom
TP22  Test Point  [TP35S_SMD]  12.93 77.45 0 bottom
TP23  Test Point  [TP35S_SMD]  10.52 77.53 270 bottom
TP24  Test Point  [TP35S_SMD]  67.8 37.36 270 bottom
TP25  Test Point  [TP35S_SMD]  65.61 37.34 180 bottom
TP26  Test Point  [TP35S_SMD]  63.55 37.31 180 bottom
TP27  Test Point  [TP35S_SMD]  55.36 22.25 270 bottom
TP28  Test Point  [TP35S_SMD]  55.36 24.5 0 bottom
TP29  Test Point  [TP35S_SMD]  7.01 45.86 180 bottom
TP30  Test Point  [TP35S_SMD]  53.12 24.49 270 bottom
TP31  Test Point  [TP35S_SMD]  110.19 33.06 90 bottom
TP32  Test Point  [TP35S_SMD]  96.31 14.21 180 bottom
TP33  Test Point  [TP35S_SMD]  60.84 19.57 180 bottom
TP34  Test Point  [TP35S_SMD]  36.29 44.99 180 bottom
TP35  Test Point  [TP35S_SMD]  62.56 74.16 180 bottom
TP36  Test Point  [TP35S_SMD]  70.49 73.44 180 bottom
TP37  Test Point  [TP35S_SMD]  67.36 74.01 270 bottom
TP38  Test Point  [TP35S_SMD]  65.71 75.8 270 bottom
TP39  Test Point  [TP35S_SMD]  72.78 73.34 0 bottom
TP40  Test Point  [TP35S_SMD]  65.03 73.29 0 bottom
U1  SGM61630A  [SOP8_1D27_5X4X1_7MM]  72.65 39.29 180 bottom
U2  SGM61630A  [SOP8_1D27_5X4X1_7MM]  52.22 39.31 180 bottom
U3  SGM7222YWQ10/TR  [WQFN10_0D4_1_8X1_4X0_75MM]  60.28 29.79 90 top
U4  LAN9512I-JZX  [QFN64_0D5_9X9MM]  50.59 32.23 90 top
U5  USB2514Bi-AEZG-TR  [QFN36_0D5_6X6MM]  98.4 69.45 180 top
U6  UM805RE  [SOT_143]  79.57 74.16 270 bottom
U7  MIC2026-1YM-TR  [SOIC8_1D27_4_9X3_9MM]  107.4 71.85 270 top
U8  TPD4E05U06DQAR  [USON10_0D5_2D5X1X0D5MM]  108.82 49.36 180 bottom
U9  TPD4E05U06DQAR  [USON10_0D5_2D5X1X0D5MM]  105.39 48.83 180 bottom
U10  TPD4E05U06DQAR  [USON10_0D5_2D5X1X0D5MM]  102.06 47.84 180 top
U11  TPD4E05U06DQAR  [USON10_0D5_2D5X1X0D5MM]  49.05 22.56 180 top
U12  PCA9535RGER  [VQFN24_0D5_4X4X1MM]  29.43 70.61 90 top
U13  XC6206P332MR-G  [SOT23]  60.91 4.61 180 top
U14  SGM7222YWQ10/TR  [WQFN10_0D4_1_8X1_4X0_75MM]  37.46 24.45 270 bottom
U15  CH343P  [QFN16G_0D5_3X3X0_85MM]  36.89 54.44 0 top
U16  PCF8563T/5,518  [SOIC8_1D27_4_9X3_9MM]  13.21 70.4 270 top
U17  AT24C256C-SSHL-T  [SOIC8_1D27_4_9X3_9MM]  64.82 79.48 270 bottom
U18  74LVC1G07GW  [SOT353]  16.13 73.39 90 bottom
U19  ATECC608A-MAHDA-S  [UDFN8_0D5_2X3X0_6MM]  36.12 70.88 90 top
U20  TPD4E05U06DQAR  [USON10_0D5_2D5X1X0D5MM]  8.69 61.04 270 bottom
U21  XC6206P182MR  [SOT23]  33.76 66.76 180 top
U22  B0505S-1WR3  [CONVERTER4P_2R54_11R6X6MM]  59.04 19.57 270 top
U23  SY6280AAC  [SOT23-5]  72.75 20.65 0 top
U24  TPT7487  [SOIC16_1R27_10R3X7R5MM]  89.12 19.12 0 bottom
U25  74HC86T14-13  [TSSOP14_0D65_5X4D4X1D2MM]  35.42 61.12 180 top
U26  TPT7487  [SOIC16_1R27_10R3X7R5MM]  78.16 19.13 0 bottom
U27  TPT7487  [SOIC16_1R27_10R3X7R5MM]  67.13 19.13 0 bottom
U28  MQ7813T120  [MOUDLE8P_2D54_27_9X17_8MM]  19.9 32.71 180 top
U29  TPD4E05U06DQAR  [USON10_0D5_2D5X1X0D5MM]  16.53 39.8 0 bottom
U30  TPD4E05U06DQAR  [USON10_0D5_2D5X1X0D5MM]  22.49 39.95 0 bottom
U31  SY6280AAC  [SOT23-5]  32.7 74.31 270 bottom
U32  TPD4E05U06DQAR  [USON10_0D5_2D5X1X0D5MM]  8.69 58.06 270 bottom
U33  FM93C66A-SO-T-G  [SOP8_1D27_4_9X3_9MM]  32.84 34.75 270 bottom
U34  TPD4E05U06DQAR  [USON10_0D5_2D5X1X0D5MM]  8.69 55.01 270 bottom
U*  U*  []  66.5 57.25 270 bottom
X1  25MHz  [X4-SMD-3_2X2_5X1_0MM]  53.33 23.3 180 top
X2  24MHz 18pF  [X4-SMD-3_2X2_5X1_0MM]  101.83 62.54 90 top
X3  32.768kHz 12.5pF  [X2_SMD_3_2X1_5MM]  7.26 68.86 180 top

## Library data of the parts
B1 = ACTIVE BUZZER
C1 C3 C5-C13 C15-C18 C20-C24 C28-C31 C33 C34 C42 C44 C48 C56-C58 C69 C71 C73-C82 C84 C86-C89 C92 C95 C97 C99 C102-C110 C112-C118 C124 C145-C159 C161-C163 C166-C169 C502 C505-C507 = CC
C2 C126 C127 C144 C499 = CT
C14 C19 C32 C37 C38 C40 C41 C43 C45-C47 C49-C55 C59-C68 C83 C85 C90 C91 C93 C94 C96 C98 C100 C101 C111 C119 C120 C125 C131 C136-C143 C160 C165 C500 C501 C504 = CC: signal model: DEFAULT_CAPACITOR_100000pF_1_2
C35 C36 = CC: signal model: DEFAULT_CAPACITOR_1e+06pF_1_2
C70 C72 = CC: signal model: DEFAULT_CAPACITOR_10000pF_1_2
C121-C123 C128 = CC: signal model: DEFAULT_CAPACITOR_33.000000pF_1_2
C130 C132-C134 C164 C503 = CC: signal model: DEFAULT_CAPACITOR_4.7e+06pF_1_2
D1-D4 D6 D7 D9-D11 D13 D24-D27 D29 D63 = D
D5 D12 D14-D23 D28 D30-D33 D36 D37 D39 D41 D42 D44 D46-D48 D50 D61 D62 = DIODE TVS BI-DIR
D8 D34 = DIODE TVS
D51 D52 = BRIDGE RECTIFIERS DF
F1 F2 = Fuse
FB1-FB6 FB9 FB10 FB26 FB27 = FB
G1 = gdt_2p
J1 J12 = Header 1x2
J2 J13 J19 J61 = Header 2x7 13P
J3 = SOLDERING TERMINAL 4P
J4 = CM4_CON_A
J5 = CM4_CON_B
J6 = Toggle Switch_2CH
J8 = Dual USB A
J9 = HDMI_Type A_19P_320010999
J10 = RJ45_HanRun_HY911105T
J11 = USB2.0_Type C_16+4P-Vert
J14 J15 = MINI_PCIE_52P
J16 = SIM Holder 7P
J18 = RJ45_LPJE101AGNL
J21-J23 = Terminal 3P
J24 = FPC 22+4P
J25 = JST_10+2P
J62 = PCIe_M.2_Key M_75Pin
L2 L3 L15 L18 = L
L4 L5 L19-L22 = CL
L11 = L: signal model: Graser_L11
L16 = CLT
MH1-MH4 MH6 MH7 MH10-MH14 = MHole
OSC1 = OSC_4P
Q1 Q4 = PMOS_9P
Q2 = PNP
Q3 Q5 = NMOS_123
R2-R5 R7-R25 R27 R28 R30-R40 R42 R44-R47 R50-R56 R59 R64 R69 R71-R73 R78-R85 R88-R90 R92-R111 R113-R120 R122 R123 R125 R127 R129-R131 R135 R136 R138-R140 R143 R145 R147 R148 R150-R164 R173-R178 R181 R530-R532 R573 R632 R633 R651-R654 = R
R26 R29 R48 R49 R57 R70 R112 = R: signal model: DEFAULT_RESISTOR_0.001OHM_1_2
R41 R43 R60-R63 R65-R68 R74 R75 R124 R132 R133 R141 R142 R149 = R: signal model: DEFAULT_RESISTOR_10000OHM_1_2
R58 = R: signal model: DEFAULT_RESISTOR_12000OHM_1_2
R126 R128 R134 R137 R144 R146 = R: signal model: DEFAULT_RESISTOR_33.000000OHM_1_2
R182 R183 = VDR
SW1 = BUTTON 2+2P
T1 = LP82441ANL
TP1-TP40 = Test Point
U1 U2 = SGM61630A
U3 U14 = SGM7222
U4 = LAN9512/4
U5 = USB251xB/xBi
U6 = UM805_4P
U7 = MIC2026
U8 U9 = TPD4E05U06DQAR: signal model: TPD4E05U06DQAR_USON10_0D5_2D5X1X0D5MM_TPD4E05U06DQAR_TPD4E05U06DQAR
U10 U11 U20 U29 U30 U32 U34 = TPD4E05U06DQAR
U12 = PCA9535RGE
U13 U21 = LDO_3P
U15 = CH343P
U16 = DS1337
U17 = CAT24C256
U18 = SN74LVC1G07DCK
U19 = ATECC608A
U22 = Isolate DCDC
U23 U31 = SY6280
U24 U26 U27 = ISO3082DW
U25 = SN74AHC86
U28 = Module_MQ7813
U33 = FM93C66A
X1 X2 = XTAL_4P
X3 = XTAL_2P

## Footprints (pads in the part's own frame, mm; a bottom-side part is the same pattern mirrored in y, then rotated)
AVX_B
  rrect 1.143x2.286 smd: 1(-1.46,0) 2(1.46,0)
BUTTON4P_7_2X7_5X7MM
  round 2 hole 1.1: 1(-2.25,2.45) 2(2.25,2.45)
  round 2 hole 1.2: 3(3.6,0) 4(-3.6,0)
BUZZER2P_8D4_9_6X9_6X5_5MM
  rrect 1.6x3.2 smd: 1(0,4.6) 2(0,-4.6)
C0201
  rrect 0.279x0.318 smd: 1(-0.255,0) 2(0.255,0)
C0402
  rrect 0.5x0.5 smd: 1(-0.463,0) 2(0.463,0)
C0603
  rrect 0.889x0.889 smd: 1(-0.762,0) 2(0.762,0)
C0805
  rrect 1.016x1.397 smd: 1(-0.889,0) 2(0.889,0)
C1206
  rect 1.397x1.626 smd: 1(-1.41,0) 2(1.41,0)
CAE-10_5X10_5X10_5MM-S
  rect 4.5x1.5 smd: 1(-4.3,0) 2(4.3,0)
CAP_5D0_9X3X12MM
  round 1.6 hole 0.9: 1(-2.35,-0.8) 2(2.35,0.8)
CON_MINIPEX_075_SMT_RA_M2_KEYM
  round 0.13 hole 1.1 unplated: (-10,-1.335)
  round 0.13 hole 1.6 unplated: (10,-1.335)
  rect 0.28x1.4 smd: 1(-9.25,3.815) 3(-8.75,3.815) 5(-8.25,3.815) 7(-7.75,3.815) 9(-7.25,3.815) 11(-6.75,3.815) 13(-6.25,3.815) 15(-5.75,3.815) 17(-5.25,3.815) 19(-4.75,3.815) 21(-4.25,3.815) 23(-3.75,3.815) 25(-3.25,3.815) 27(-2.75,3.815) 29(-2.25,3.815) 31(-1.75,3.815) 33(-1.25,3.815) 35(-0.75,3.815) 37(-0.25,3.815) 39(0.25,3.815) 41(0.75,3.815) 43(1.25,3.815) 45(1.75,3.815) 47(2.25,3.815) 49(2.75,3.815) 51(3.25,3.815) 53(3.75,3.815) 55(4.25,3.815) 57(4.75,3.815) 67(7.25,3.815) 69(7.75,3.815) 71(8.25,3.815) 73(8.75,3.815) 75(9.25,3.815)
  rect 0.28x1.05 smd: 2(-9,-3.71) 4(-8.5,-3.71) 6(-8,-3.71) 8(-7.5,-3.71) 10(-7,-3.71) 12(-6.5,-3.71) 14(-6,-3.71) 16(-5.5,-3.71) 18(-5,-3.71) 20(-4.5,-3.71) 22(-4,-3.71) 24(-3.5,-3.71) 26(-3,-3.71) 28(-2.5,-3.71) 30(-2,-3.71) 32(-1.5,-3.71) 34(-1,-3.71) 36(-0.5,-3.71) 38(0,-3.71) 40(0.5,-3.71) 42(1,-3.71) 44(1.5,-3.71) 46(2,-3.71) 48(2.5,-3.71) 50(3,-3.71) 52(3.5,-3.71) 54(4,-3.71) 56(4.5,-3.71) 58(5,-3.71) 68(7.5,-3.71) 70(8,-3.71) 72(8.5,-3.71) 74(9,-3.71)
  rect 1.1x2.08 smd: 76(-10.4,3.28) 77(10.4,3.28)
CONVERTER4P_2R54_11R6X6MM
  oval 1.3x0.8 hole 0.75x0.55: 1(-3.81,0) 2(-1.27,0) 3(1.27,0) 4(3.81,0)
D0402
  rrect 0.5x0.5 smd: 1(-0.463,0) 2(0.463,0)
DF40_100P_0D4_22_6X3_38X1_5MM
  rrect 0.7x0.2 smd: 1(1.54,-9.8) 2(-1.54,-9.8) 3(1.54,-9.4) 4(-1.54,-9.4) 5(1.54,-9) 6(-1.54,-9) 7(1.54,-8.6) 8(-1.54,-8.6) 9(1.54,-8.2) 10(-1.54,-8.2) 11(1.54,-7.8) 12(-1.54,-7.8) 13(1.54,-7.4) 14(-1.54,-7.4) 15(1.54,-7) 16(-1.54,-7) 17(1.54,-6.6) 18(-1.54,-6.6) 19(1.54,-6.2) 20(-1.54,-6.2) 21(1.54,-5.8) 22(-1.54,-5.8) 23(1.54,-5.4) 24(-1.54,-5.4) 25(1.54,-5) 26(-1.54,-5) 27(1.54,-4.6) 28(-1.54,-4.6) 29(1.54,-4.2) 30(-1.54,-4.2) 31(1.54,-3.8) 32(-1.54,-3.8) 33(1.54,-3.4) 34(-1.54,-3.4) 35(1.54,-3) 36(-1.54,-3) 37(1.54,-2.6) 38(-1.54,-2.6) 39(1.54,-2.2) 40(-1.54,-2.2) 41(1.54,-1.8) 42(-1.54,-1.8) 43(1.54,-1.4) 44(-1.54,-1.4) 45(1.54,-1) 46(-1.54,-1) 47(1.54,-0.6) 48(-1.54,-0.6) 49(1.54,-0.2) 50(-1.54,-0.2) 51(1.54,0.2) 52(-1.54,0.2) 53(1.54,0.6) 54(-1.54,0.6) 55(1.54,1) 56(-1.54,1) 57(1.54,1.4) 58(-1.54,1.4) 59(1.54,1.8) 60(-1.54,1.8) 61(1.54,2.2) 62(-1.54,2.2) 63(1.54,2.6) 64(-1.54,2.6) 65(1.54,3) 66(-1.54,3) 67(1.54,3.4) 68(-1.54,3.4) 69(1.54,3.8) 70(-1.54,3.8) 71(1.54,4.2) 72(-1.54,4.2) 73(1.54,4.6) 74(-1.54,4.6) 75(1.54,5) 76(-1.54,5) 77(1.54,5.4) 78(-1.54,5.4) 79(1.54,5.8) 80(-1.54,5.8) 81(1.54,6.2) 82(-1.54,6.2) 83(1.54,6.6) 84(-1.54,6.6) 85(1.54,7) 86(-1.54,7) 87(1.54,7.4) 88(-1.54,7.4) 89(1.54,7.8) 90(-1.54,7.8) 91(1.54,8.2) 92(-1.54,8.2) 93(1.54,8.6) 94(-1.54,8.6) 95(1.54,9) 96(-1.54,9) 97(1.54,9.4) 98(-1.54,9.4) 99(1.54,9.8) 100(-1.54,9.8)
DF40_100P_0D4_22_6X3_38X1_5MM_101_200
  rrect 0.7x0.2 smd: 101(1.54,-9.8) 102(-1.54,-9.8) 103(1.54,-9.4) 104(-1.54,-9.4) 105(1.54,-9) 106(-1.54,-9) 107(1.54,-8.6) 108(-1.54,-8.6) 109(1.54,-8.2) 110(-1.54,-8.2) 111(1.54,-7.8) 112(-1.54,-7.8) 113(1.54,-7.4) 114(-1.54,-7.4) 115(1.54,-7) 116(-1.54,-7) 117(1.54,-6.6) 118(-1.54,-6.6) 119(1.54,-6.2) 120(-1.54,-6.2) 121(1.54,-5.8) 122(-1.54,-5.8) 123(1.54,-5.4) 124(-1.54,-5.4) 125(1.54,-5) 126(-1.54,-5) 127(1.54,-4.6) 128(-1.54,-4.6) 129(1.54,-4.2) 130(-1.54,-4.2) 131(1.54,-3.8) 132(-1.54,-3.8) 133(1.54,-3.4) 134(-1.54,-3.4) 135(1.54,-3) 136(-1.54,-3) 137(1.54,-2.6) 138(-1.54,-2.6) 139(1.54,-2.2) 140(-1.54,-2.2) 141(1.54,-1.8) 142(-1.54,-1.8) 143(1.54,-1.4) 144(-1.54,-1.4) 145(1.54,-1) 146(-1.54,-1) 147(1.54,-0.6) 148(-1.54,-0.6) 149(1.54,-0.2) 150(-1.54,-0.2) 151(1.54,0.2) 152(-1.54,0.2) 153(1.54,0.6) 154(-1.54,0.6) 155(1.54,1) 156(-1.54,1) 157(1.54,1.4) 158(-1.54,1.4) 159(1.54,1.8) 160(-1.54,1.8) 161(1.54,2.2) 162(-1.54,2.2) 163(1.54,2.6) 164(-1.54,2.6) 165(1.54,3) 166(-1.54,3) 167(1.54,3.4) 168(-1.54,3.4) 169(1.54,3.8) 170(-1.54,3.8) 171(1.54,4.2) 172(-1.54,4.2) 173(1.54,4.6) 174(-1.54,4.6) 175(1.54,5) 176(-1.54,5) 177(1.54,5.4) 178(-1.54,5.4) 179(1.54,5.8) 180(-1.54,5.8) 181(1.54,6.2) 182(-1.54,6.2) 183(1.54,6.6) 184(-1.54,6.6) 185(1.54,7) 186(-1.54,7) 187(1.54,7.4) 188(-1.54,7.4) 189(1.54,7.8) 190(-1.54,7.8) 191(1.54,8.2) 192(-1.54,8.2) 193(1.54,8.6) 194(-1.54,8.6) 195(1.54,9) 196(-1.54,9) 197(1.54,9.4) 198(-1.54,9.4) 199(1.54,9.8) 200(-1.54,9.8)
DO_214AA_SMB
  rrect 2.032x2.286 smd: 1(-2.032,0) 2(2.032,0)
DO_214AB_SMC
  rrect 2.286x4.064 smd: 1(-3.683,0) 2(3.683,0)
ELECTRO_SMD_6_6X6_6MM
  rrect 1x3 smd: 1(0,-2.45) 2(0,2.45)
F0603
  rrect 1x1 smd: 1(-0.8,0) 2(0.8,0)
FPC22_0D5_16_7X3_5X3_95MM_90D
  rrect 0.5x1.5 smd: 1(5.25,1.1) 2(4.75,-1.1) 3(4.25,1.1) 4(3.75,-1.1) 5(3.25,1.1) 6(2.75,-1.1) 7(2.25,1.1) 8(1.75,-1.1) 9(1.25,1.1) 10(0.75,-1.1) 11(0.25,1.1) 12(-0.25,-1.1) 13(-0.75,1.1) 14(-1.25,-1.1) 15(-1.75,1.1) 16(-2.25,-1.1) 17(-2.75,1.1) 18(-3.25,-1.1) 19(-3.75,1.1) 20(-4.25,-1.1) 21(-4.75,1.1) 22(-5.25,-1.1)
  rrect 0.6x1.5 smd: SH1(-6.3,1.1) SH2(-6.3,-1.1) SH3(6.3,-1.1) SH4(6.3,1.1)
FUSE2P_HOLDER_9_73X5_03X3_81MM
  rrect 4.24x3.81 smd: 1(-3.185,0) 2(3.185,0)
GDT2P_4D0_4_5X3_2X2_7MM
  rrect 1x3.4 smd: 1(-2.25,0) 2(2.25,0)
HDMI19P_1D155_23_1X7_7X16_4MM
  round 1.7 hole 1.7 unplated: (-2,13.25) (1.5,0)
  round 0.8 hole 0.55: 1(0.5,1.9) 2(-0.5,2.478) 3(0.5,3.055) 4(-0.5,3.633) 5(0.5,4.21) 6(-0.5,4.788) 7(0.5,5.365) 8(-0.5,5.943) 9(0.5,6.52) 10(-0.5,7.098) 11(0.5,7.675) 12(-0.5,8.253) 13(0.5,8.83) 14(-0.5,9.408) 15(0.5,9.985) 16(-0.5,10.563) 17(0.5,11.14) 18(-0.5,11.718) 19(0.5,12.295)
  oval 1.7x3.4 hole 0.9x2.7: 20(-3.25,1.15) 21(-3.25,10.15) 22(3.25,3.75) 23(3.25,13.25)
HEADER2P_1D25_DIP
  round 0.9 hole 0.55: 1(0.625,0) 2(-0.625,0)
HEADER2X7P_1D27_SMD_NP_EPT14
  round 1.05 hole 1.05 unplated: (-3.125,0) (3.125,0)
  rrect 0.74x2.4 smd: 1(-3.81,-1.95) 2(-3.81,1.95) 3(-2.54,-1.95) 4(-2.54,1.95) 5(-1.27,-1.95) 6(-1.27,1.95) 7(0,-1.95) 8(0,1.95) 9(1.27,-1.95) 10(1.27,1.95) 11(2.54,-1.95) 12(2.54,1.95) 13(3.81,-1.95)
JST10_2P_1D0_12_35X3_2X4_5MM
  rrect 0.5x1.2 smd: 1(-4.5,0) 2(-3.5,0) 3(-2.5,0) 4(-1.5,0) 5(-0.5,0) 6(0.5,0) 7(1.5,0) 8(2.5,0) 9(3.5,0) 10(4.5,0)
  rrect 0.8x1.5 smd: S1(-5.7,-2.95) S2(5.7,-2.95)
L2P_7D3_15_8X8X10MM
  round 1.4 hole 1: 1(-3.65,0) 2(3.65,0)
L4P_0_85X0_65MM
  rrect 0.3x0.3 smd: 1(-0.25,-0.3) 2(-0.25,0.3) 3(0.25,0.3) 4(0.25,-0.3)
L4P_10X8_7X6_5MM
  rrect 2.7x2.7 smd: 1(3.1,-3.8) 2(-3.1,-3.8) 3(-3.1,3.8) 4(3.1,3.8)
L4X4MM
  rect 1.6x3 smd: 1(-1.5,0) 2(1.5,0)
L6_6X7X1_6MM
  rrect 1.9x3.3 smd: 1(-2.85,0) 2(2.85,0)
L0402
  rrect 0.5x0.5 smd: 1(-0.463,0) 2(0.463,0)
L0603
  rrect 0.889x0.889 smd: 1(-0.762,0) 2(0.762,0)
L4242
  rrect 1.55x3.1 smd: 1(-1.75,0) 2(1.75,0)
MOUDLE8P_2D54_27_9X17_8MM
  round 1.9 hole 1.2: 1(-11.43,-7.62) 2(-8.89,-7.62) 3(8.89,-7.62) 4(11.43,-7.62) 5(11.43,7.62) 6(8.89,7.62) 7(-8.89,7.62) 8(-11.43,7.62)
PCIE52_0D8_56X30_2X4MM
  round 1.1 hole 1.1 unplated: (0,-12.5)
  round 1.6 hole 1.6 unplated: (0,12.5)
  rect 2x0.55 smd: 1(-4.1,11.8) 2(4.1,11.4) 3(-4.1,11) 4(4.1,10.6) 5(-4.1,10.2) 6(4.1,9.8) 7(-4.1,9.4) 8(4.1,9) 9(-4.1,8.6) 10(4.1,8.2) 11(-4.1,7.8) 12(4.1,7.4) 13(-4.1,7) 14(4.1,6.6) 15(-4.1,6.2) 16(4.1,5.8) 17(-4.1,2.2) 18(4.1,1.8) 19(-4.1,1.4) 20(4.1,1) 21(-4.1,0.6) 22(4.1,0.2) 23(-4.1,-0.2) 24(4.1,-0.6) 25(-4.1,-1) 26(4.1,-1.4) 27(-4.1,-1.8) 28(4.1,-2.2) 29(-4.1,-2.6) 30(4.1,-3) 31(-4.1,-3.4) 32(4.1,-3.8) 33(-4.1,-4.2) 34(4.1,-4.6) 35(-4.1,-5) 36(4.1,-5.4) 37(-4.1,-5.8) 38(4.1,-6.2) 39(-4.1,-6.6) 40(4.1,-7) 41(-4.1,-7.4) 42(4.1,-7.8) 43(-4.1,-8.2) 44(4.1,-8.6) 45(-4.1,-9) 46(4.1,-9.4) 47(-4.1,-9.8) 48(4.1,-10.2) 49(-4.1,-10.6) 50(4.1,-11) 51(-4.1,-11.4) 52(4.1,-11.8)
  rect 3.2x2.3 smd: 53(-3.5,-14.65) 54(-3.5,14.65)
PTH_3_1MM_8
  round 8.128 hole 3.1: 1(0,0)
PTH_3_73MM_5D8_PASTE
  round 4.3 hole 3.73: 1(0,0)
PTH_4_2MM_5D8
  round 5.8 hole 4.2: 1(0,0)
PTH_4_3MM_6D0
  round 6 hole 4.3: 1(0,0)
QFN16G_0D5_3X3X0_85MM
  rrect 0.6x0.25 smd: 1(-1.475,0.75) 2(-1.475,0.25) 3(-1.475,-0.25) 4(-1.475,-0.75) 9(1.475,-0.75) 10(1.475,-0.25) 11(1.475,0.25) 12(1.475,0.75)
  rrect 0.25x0.6 smd: 5(-0.75,-1.475) 6(-0.25,-1.475) 7(0.25,-1.475) 8(0.75,-1.475) 13(0.75,1.475) 14(0.25,1.475) 15(-0.25,1.475) 16(-0.75,1.475)
  rrect 1.6x1.6 smd: 17(0,0)
QFN36_0D5_6X6MM
  rrect 0.9x0.3 smd: 1(-2.85,2) 2(-2.85,1.5) 3(-2.85,1) 4(-2.85,0.5) 5(-2.85,0) 6(-2.85,-0.5) 7(-2.85,-1) 8(-2.85,-1.5) 9(-2.85,-2) 19(2.85,-2) 20(2.85,-1.5) 21(2.85,-1) 22(2.85,-0.5) 23(2.85,0) 24(2.85,0.5) 25(2.85,1) 26(2.85,1.5) 27(2.85,2)
  rrect 0.3x0.9 smd: 10(-2,-2.85) 11(-1.5,-2.85) 12(-1,-2.85) 13(-0.5,-2.85) 14(0,-2.85) 15(0.5,-2.85) 16(1,-2.85) 17(1.5,-2.85) 18(2,-2.85) 28(2,2.85) 29(1.5,2.85) 30(1,2.85) 31(0.5,2.85) 32(0,2.85) 33(-0.5,2.85) 34(-1,2.85) 35(-1.5,2.85) 36(-2,2.85)
  rrect 3.7x3.7 smd: 37(0,0)
QFN64_0D5_9X9MM
  rrect 0.25x0.7 smd: 1(-3.75,-4.45) 2(-3.25,-4.45) 3(-2.75,-4.45) 4(-2.25,-4.45) 5(-1.75,-4.45) 6(-1.25,-4.45) 7(-0.75,-4.45) 8(-0.25,-4.45) 9(0.25,-4.45) 10(0.75,-4.45) 11(1.25,-4.45) 12(1.75,-4.45) 13(2.25,-4.45) 14(2.75,-4.45) 15(3.25,-4.45) 16(3.75,-4.45) 33(3.75,4.45) 34(3.25,4.45) 35(2.75,4.45) 36(2.25,4.45) 37(1.75,4.45) 38(1.25,4.45) 39(0.75,4.45) 40(0.25,4.45) 41(-0.25,4.45) 42(-0.75,4.45) 43(-1.25,4.45) 44(-1.75,4.45) 45(-2.25,4.45) 46(-2.75,4.45) 47(-3.25,4.45) 48(-3.75,4.45)
  rrect 0.7x0.25 smd: 17(4.45,-3.75) 18(4.45,-3.25) 19(4.45,-2.75) 20(4.45,-2.25) 21(4.45,-1.75) 22(4.45,-1.25) 23(4.45,-0.75) 24(4.45,-0.25) 25(4.45,0.25) 26(4.45,0.75) 27(4.45,1.25) 28(4.45,1.75) 29(4.45,2.25) 30(4.45,2.75) 31(4.45,3.25) 32(4.45,3.75) 49(-4.45,3.75) 50(-4.45,3.25) 51(-4.45,2.75) 52(-4.45,2.25) 53(-4.45,1.75) 54(-4.45,1.25) 55(-4.45,0.75) 56(-4.45,0.25) 57(-4.45,-0.25) 58(-4.45,-0.75) 59(-4.45,-1.25) 60(-4.45,-1.75) 61(-4.45,-2.25) 62(-4.45,-2.75) 63(-4.45,-3.25) 64(-4.45,-3.75)
  rrect 5x5 smd: 65(0,0)
R0201
  rrect 0.279x0.318 smd: 1(-0.255,0) 2(0.255,0)
R0402
  rrect 0.5x0.5 smd: 1(-0.463,0) 2(0.463,0)
R0603
  rrect 0.889x0.889 smd: 1(-0.762,0) 2(0.762,0)
R0805
  rrect 1.016x1.397 smd: 1(-0.889,0) 2(0.889,0)
R1206
  rect 1.397x1.626 smd: 1(-1.41,0) 2(1.41,0)
RJ45-7499010211A
  round 1.016 hole 3.251 unplated: (-1.27,-6.35) (10.16,-6.35)
  rect 1.524x1.524 hole 1.016: 1(0,0)
  round 1.524 hole 1.016: 2(1.27,2.54) 3(2.54,0) 4(3.81,2.54) 5(5.08,0) 6(6.35,2.54) 7(7.62,0) 8(8.89,2.54) 9(-1.88,-11.252) 10(0.66,-9.728) 11(8.23,-11.252) 12(10.77,-9.728)
  round 2.286 hole 1.6: 13(-3.429,-3.302) 14(12.319,-3.302)
RJ45_12_2P_2D54_16_3X15_8X12_85MM
  round 3.25 hole 3.25 unplated: (-6.35,0) (6.35,0)
  round 1.3 hole 0.9: 1(-4.445,9.12) 2(-3.175,7.34) 3(-1.905,9.12) 4(-0.635,7.34) 5(0.635,9.12) 6(1.905,7.34) 7(3.175,9.12) 8(4.445,7.34)
  round 1.6 hole 1.2: 9(6.595,5.1) 10(4.305,5.1) 11(-4.305,5.1) 12(-6.595,5.1)
  round 1.9 hole 1.4: 13(8.05,3.56) 14(-8.05,3.56)
SIM6_2P_2D54_25X31X3_55MM
  rrect 1.4x2.3 smd: C1(0,23.2) C2(2.54,23.2) C3(5.08,23.2) C5(0,0) C6(2.54,0) C7(5.08,0) K1(12.37,0) K2(12.37,23.2)
SMD4P_4D7X3D8MM
  rrect 1.2x1.9 smd: 1(1.2,3) 2(-1.2,3) 3(-1.2,-3) 4(1.2,-3)
SOD_123
  rrect 1.397x1.397 smd: 1(-1.651,0) 2(1.651,0)
SOD_323
  rrect 1x0.8 smd: 1(-1.2,0) 2(1.2,0)
SOD_523
  rrect 0.762x0.7 smd: 1(-0.8,0) 2(0.8,0)
SOIC8_1D27_4_9X3_9MM
  rrect 0.6x1.55 smd: 1(-1.905,-2.7) 2(-0.635,-2.7) 3(0.635,-2.7) 4(1.905,-2.7) 5(1.905,2.7) 6(0.635,2.7) 7(-0.635,2.7) 8(-1.905,2.7)
SOIC16_1R27_10R3X7R5MM
  rrect 0.6x1.6 smd: 1(-4.445,-4.825) 2(-3.175,-4.825) 3(-1.905,-4.825) 4(-0.635,-4.825) 5(0.635,-4.825) 6(1.905,-4.825) 7(3.175,-4.825) 8(4.445,-4.825) 9(4.445,4.825) 10(3.175,4.825) 11(1.905,4.825) 12(0.635,4.825) 13(-0.635,4.825) 14(-1.905,4.825) 15(-3.175,4.825) 16(-4.445,4.825)
SOLDERING_TERMINAL_4P_9X6_3X5MM
  round 2.5 hole 1.5: 1(-2.5,2.75) 2(-2.5,-2.75) 3(2.5,-2.75) 4(2.5,2.75)
SON8P_1D27_5X6X1MM
  rrect 0.8x0.65 smd: 1(-2.802,1.905) 2(-2.802,0.635) 3(-2.802,-0.635) 4(-2.802,-1.905) 5(2.802,-1.905) 6(2.802,-0.635) 7(2.802,0.635) 8(2.802,1.905)
  rrect 4.27x4.46 smd: 9(0.337,0)
SOP8_1D27_4_9X3_9MM
  rrect 0.6x1.55 smd: 1(-1.905,-2.7) 2(-0.635,-2.7) 3(0.635,-2.7) 4(1.905,-2.7) 5(1.905,2.7) 6(0.635,2.7) 7(-0.635,2.7) 8(-1.905,2.7)
SOP8_1D27_5X4X1_7MM
  rrect 1.375x0.6 smd: 1(-2.51,1.905) 2(-2.51,0.635) 3(-2.51,-0.635) 4(-2.51,-1.905) 5(2.51,-1.905) 6(2.51,-0.635) 7(2.51,0.635) 8(2.51,1.905)
  rrect 2.35x3.25 smd: 9(0,0)
SOT23
  rrect 1.016x1.143 smd: 1(-0.889,-1.016) 2(0.889,-1.016) 3(0,1.016)
SOT23-5
  rect 0.635x1.016 smd: 1(-0.953,-1.295) 2(0,-1.295) 3(0.953,-1.295) 4(0.953,1.295) 5(-0.953,1.295)
SOT353
  rrect 0.3x0.7 smd: 1(-0.65,-1) 2(0,-1) 3(0.65,-1) 4(0.65,1) 5(-0.65,1)
SOT_143
  rect 1.219x1.397 smd: 1(-0.75,-1.1)
  rect 1.016x1.397 smd: 2(0.95,-1.1) 3(0.95,1.1) 4(-0.95,1.1)
ST-USB-201C
  rect 1.321x1.321 hole 0.914: A1(3.5,-5.33)
  round 1.321 hole 0.914: A2(1,-5.33) A3(-1,-5.33) A4(-3.5,-5.33) B1(3.5,-2.71) B2(1,-2.71) B3(-1,-2.71) B4(-3.5,-2.71)
  round 3 hole 2.3: S1(6.57,-5.68) S2(-6.57,-5.68) S3(-6.57,0) S4(6.57,0)
SW6P_2D5_9X3_5X3_5MM
  round 1.4 hole 0.8: 1(-2.5,-1.6) 2(0,-1.6) 3(2.5,-1.6) 4(2.5,1.6) 5(0,1.6) 6(-2.5,1.6)
TERMINAL_2P_5D08
  rect 2.6x2.6 hole 1.45: 1(-2.54,0)
  round 2.6 hole 1.45: 2(2.54,0)
TERMINAL_3P_3D5_11_6X9_2X7_3MM
  rect 1.9x1.9 hole 1.3: 1(-3.5,0)
  round 1.9 hole 1.3: 2(0,0) 3(3.5,0)
TP35S_SMD
  rrect 0.9x0.9 smd: 1(0,0)
TRF24P_1D0_15_1X7_1X4MM
  rrect 0.6x1.4 smd: 1(-5.5,-4.6) 2(-4.5,-4.6) 3(-3.5,-4.6) 4(-2.5,-4.6) 5(-1.5,-4.6) 6(-0.5,-4.6) 7(0.5,-4.6) 8(1.5,-4.6) 9(2.5,-4.6) 10(3.5,-4.6) 11(4.5,-4.6) 12(5.5,-4.6) 13(5.5,4.6) 14(4.5,4.6) 15(3.5,4.6) 16(2.5,4.6) 17(1.5,4.6) 18(0.5,4.6) 19(-0.5,4.6) 20(-1.5,4.6) 21(-2.5,4.6) 22(-3.5,4.6) 23(-4.5,4.6) 24(-5.5,4.6)
TSSOP14_0D65_5X4D4X1D2MM
  rrect 0.4x1.2 smd: 1(-1.95,-2.925) 2(-1.3,-2.925) 3(-0.65,-2.925) 4(0,-2.925) 5(0.65,-2.925) 6(1.3,-2.925) 7(1.95,-2.925) 8(1.95,2.925) 9(1.3,2.925) 10(0.65,2.925) 11(0,2.925) 12(-0.65,2.925) 13(-1.3,2.925) 14(-1.95,2.925)
UDFN8_0D5_2X3X0_6MM
  rrect 0.25x0.7 smd: 1(-0.75,-1.45) 2(-0.25,-1.45) 3(0.25,-1.45) 4(0.75,-1.45) 5(0.75,1.45) 6(0.25,1.45) 7(-0.25,1.45) 8(-0.75,1.45)
  rrect 1.7x1.3 smd: 9(0,0)
USB2_0_TYPE_C_14X3D16X8D94MM
  round 0.55 hole 0.4: A1(2.925,-0.375) A4(2.025,-0.375) A5(1.125,-0.375) A6(0.225,-0.375) A7(-0.675,-0.375) A9(-2.025,-0.375) A12(-2.925,-0.375) B1(-2.925,0.375) B4(-2.025,0.375) B5(-1.125,0.375) B6(-0.225,0.375) B7(0.675,0.375) B9(2.025,0.375) B12(2.925,0.375)
  oval 2.3x0.8 hole 1.8x0.5: S1(-3.05,1.43) S4(-3.05,-1.43)
  oval 1.6x0.8 hole 1.1x0.5: S2(3.05,1.43) S3(3.05,-1.43)
USON10_0D5_2D5X1X0D5MM
  oval 0.2x0.7 smd: 1(-1,-0.45) 2(-0.5,-0.45) 4(0.5,-0.45) 5(1,-0.45) 6(1,0.45) 7(0.5,0.45) 9(-0.5,0.45) 10(-1,0.45)
  rrect 0.4x0.7 smd: 3(0,-0.45) 8(0,0.45)
VQFN24_0D5_4X4X1MM
  oval 0.7x0.24 smd: 1(-1.95,1.25) 2(-1.95,0.75) 3(-1.95,0.25) 4(-1.95,-0.25) 5(-1.95,-0.75) 6(-1.95,-1.25) 13(1.95,-1.25) 14(1.95,-0.75) 15(1.95,-0.25) 16(1.95,0.25) 17(1.95,0.75) 18(1.95,1.25)
  oval 0.24x0.7 smd: 7(-1.25,-1.95) 8(-0.75,-1.95) 9(-0.25,-1.95) 10(0.25,-1.95) 11(0.75,-1.95) 12(1.25,-1.95) 19(1.25,1.95) 20(0.75,1.95) 21(0.25,1.95) 22(-0.25,1.95) 23(-0.75,1.95) 24(-1.25,1.95)
  rrect 2.5x2.5 smd: 25(0,0)
WQFN10_0D4_1_8X1_4X0_75MM
  rect 0.22x0.75 smd: 1(-0.2,-0.575)
  rect 0.22x0.65 smd: 2(0.2,-0.625) 6(0.2,0.625) 7(-0.2,0.625)
  rect 0.65x0.22 smd: 3(0.825,-0.4) 4(0.825,0) 5(0.825,0.4) 8(-0.825,0.4) 9(-0.825,0) 10(-0.825,-0.4)
X2_SMD_3_2X1_5MM
  rrect 0.762x1.524 smd: 1(-1.524,0) 2(1.524,0)
X4-SMD-3_2X2_5X1_0MM
  rect 1.321x1.067 smd: 1(-1.15,-0.925) 2(1.15,-0.925) 3(1.15,0.925) 4(-1.15,0.925)

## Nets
3V3_RS485: C136.1 C137.1 C139.1 C140.1 C142.1 R532.2 U24.1 U25.14(VCC) U26.1 U27.1
5V_ISO_INPUT: C132.1 L11.1 U23.1(OUT)
5V_ISO_OUT: C134.1 C138.1 C141.1 C143.1 R117.2 R118.1 R124.1 R133.1 R142.1 TP32.1(TP) U24.16 U26.16 U27.16
5V_TYPC: C92.1 C93.1 C94.1 C95.1 C96.1 C99.2 D21.2 J11.A4 J11.A9 J11.B4 J11.B9 R32.2 TP20.1(TP) U13.3 U15.3 U15.9
+1.8V_OUT: C34.2 J4.88 J4.90 R112.2
+3.3V_OUT: C32.1 C33.2 J4.84 J4.86 R26.2 R29.2 R181.1
